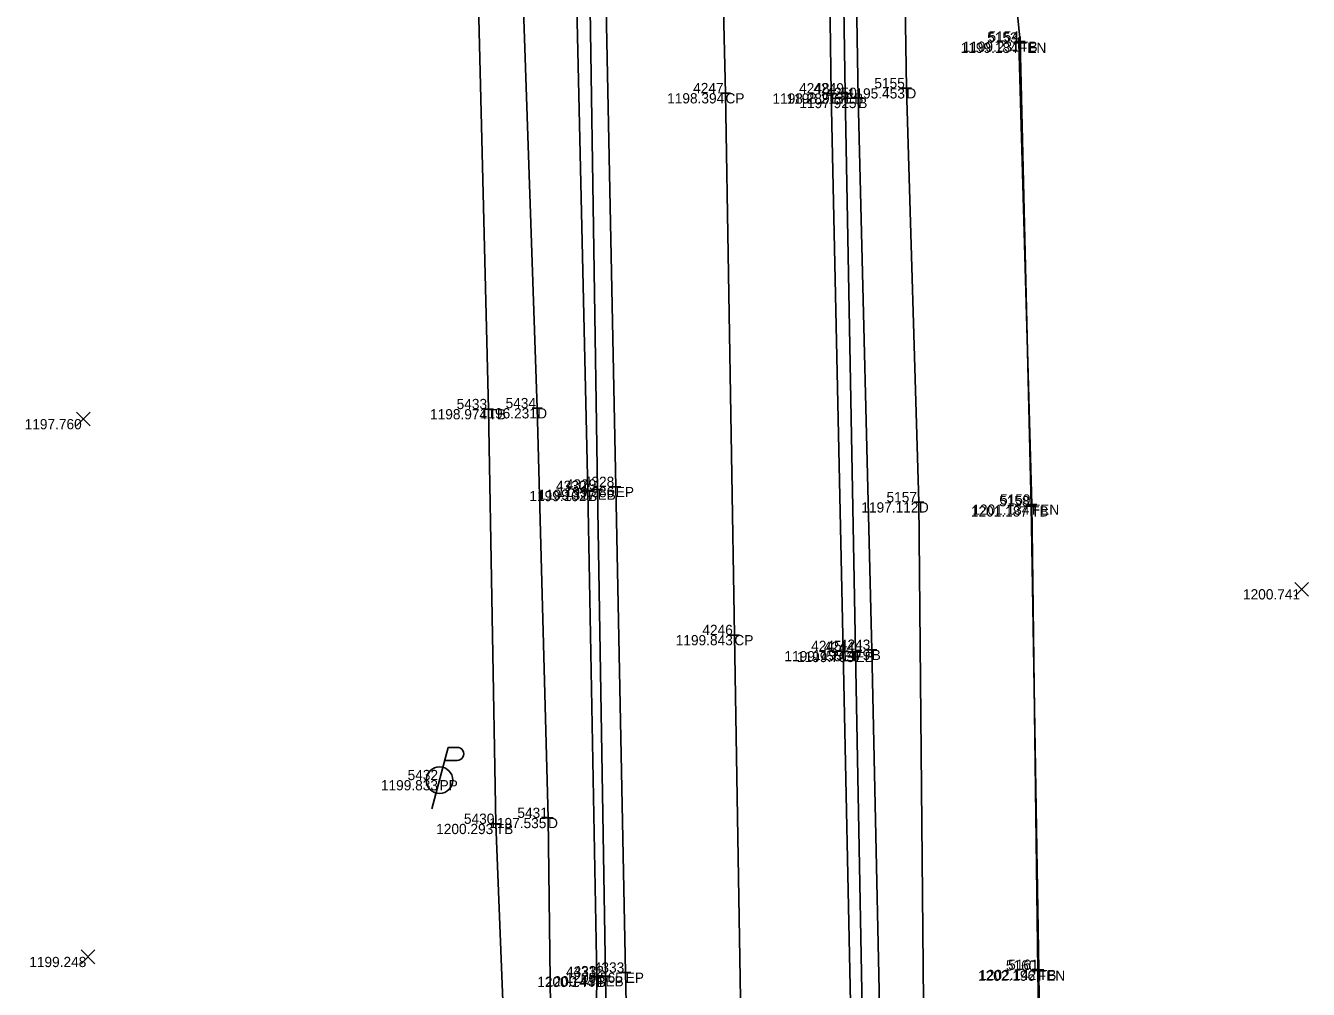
# Model space of a CAD drawing. Extents: x 2044996 to 2050343, y 455232 to 458054.
# Drawn here: x 2047551.1 to 2047676.4, y 457527.3 to 457621.4 of the extents above; entities that cross this region are included whole.
import ezdxf

# ---------------------------------------------------------------- set-up
doc = ezdxf.new("R2010")
doc.units = 0
for name, color, linetype in [('DR_X_Ditch', 7, 'Continuous'), ('DT_X_Contour_Minor', 7, 'Continuous'), ('DT_X_Contour_Text', 7, 'Continuous'), ('DT_X_Spot_Elev', 7, 'Continuous'), ('DT_X_Triangles', 7, 'Continuous'), ('DT_X_Void', 7, 'Continuous'), ('PV_X_COP', 7, 'Continuous'), ('PV_X_EOP', 7, 'Continuous'), ('PV_X_Shoulder_Aggregate', 7, 'Continuous'), ('RD_X_Fence', 7, 'Continuous'), ('SV_X_Break_Lines', 7, 'Continuous'), ('SV_X_Top_of_Bank', 7, 'Continuous'), ('UT_X_Electric_Cells', 7, 'Continuous')]:
    doc.layers.add(name, color=color, linetype=linetype)

msp = doc.modelspace()

# ---------------------------------------------------------------- linework, layer by layer
at = {"layer": 'DR_X_Ditch'}
for points in [[(2047603.88, 457240.71), (2047604.35, 457290.98), (2047605.27, 457322.96), (2047604.86, 457368.19), (2047603.19, 457417.51), (2047602.95, 457459.42), (2047602.66, 457501.84), (2047602.14, 457544.04), (2047601.08, 457584.06), (2047599.69, 457624.96), (2047599.4, 457669.27), (2047598.07, 457715.09), (2047597.97, 457762.92), (2047597.74, 457792.66), (2047596.26, 457838.2), (2047595.41, 457854.46)], [(2047635.93, 457828.45), (2047636.46, 457778.33), (2047635.67, 457731.58), (2047635.87, 457688.92), (2047636.59, 457650.58), (2047637.14, 457615.31), (2047638.36, 457574.87), (2047638.82, 457526.07), (2047639.21, 457482.92), (2047639.9, 457443.66), (2047641.24, 457398.66), (2047642.28, 457344.51), (2047644.03, 457300.89), (2047646.18, 457262.24), (2047646.96, 457237.04), (2047650.76, 457191.22), (2047650.42, 457143.89), (2047649.26, 457104.81), (2047651.9, 457052.9), (2047656.34, 457022.85)]]:
    msp.add_lwpolyline(points, dxfattribs=at)
at = {"layer": 'DT_X_Spot_Elev'}
for p, q in [((2047556.08, 457582.33), (2047557.41, 457583.67)), ((2047556.08, 457583.67), (2047557.41, 457582.33)), ((2047675.07, 457565.71), (2047676.41, 457567.05)), ((2047675.07, 457567.05), (2047676.41, 457565.71)), ((2047556.52, 457529.8), (2047557.86, 457531.14)), ((2047556.52, 457531.14), (2047557.86, 457529.8))]:
    msp.add_line(p, q, dxfattribs=at)
at = {"layer": 'DT_X_Void'}
for p, q in [((2047647.64, 457619.76), (2047648.64, 457619.76)), ((2047647.75, 457619.87), (2047648.75, 457619.87)), ((2047648.14, 457620.26), (2047648.14, 457619.26)), ((2047648.14, 457619.76), (2047648.14, 457619.76)), ((2047648.25, 457620.37), (2047648.25, 457619.37)), ((2047648.25, 457619.87), (2047648.25, 457619.87)), ((2047637.14, 457615.81), (2047637.14, 457614.81)), ((2047618.97, 457614.83), (2047619.97, 457614.83)), ((2047619.47, 457615.33), (2047619.47, 457614.33)), ((2047619.47, 457614.83), (2047619.47, 457614.83)), ((2047629.28, 457614.81), (2047630.28, 457614.81)), ((2047629.78, 457615.31), (2047629.78, 457614.31)), ((2047629.78, 457614.81), (2047629.78, 457614.81)), ((2047630.66, 457614.81), (2047631.66, 457614.81)), ((2047631.16, 457615.31), (2047631.16, 457614.31)), ((2047631.16, 457614.81), (2047631.16, 457614.81)), ((2047631.94, 457614.37), (2047632.94, 457614.37)), ((2047632.44, 457614.87), (2047632.44, 457613.87)), ((2047632.44, 457614.37), (2047632.44, 457614.37)), ((2047636.64, 457615.31), (2047637.64, 457615.31)), ((2047637.14, 457615.31), (2047637.14, 457615.31)), ((2047596.32, 457584.47), (2047596.32, 457583.47)), ((2047601.08, 457584.56), (2047601.08, 457583.56)), ((2047595.82, 457583.97), (2047596.82, 457583.97)), ((2047596.32, 457583.97), (2047596.32, 457583.97)), ((2047600.58, 457584.06), (2047601.58, 457584.06)), ((2047601.08, 457584.06), (2047601.08, 457584.06)), ((2047608.75, 457576.87), (2047608.75, 457575.87)), ((2047605.54, 457575.98), (2047606.54, 457575.98)), ((2047606.04, 457576.48), (2047606.04, 457575.48)), ((2047606.04, 457575.98), (2047606.04, 457575.98)), ((2047606.47, 457576.11), (2047607.47, 457576.11)), ((2047606.97, 457576.61), (2047606.97, 457575.61)), ((2047606.97, 457576.11), (2047606.97, 457576.11)), ((2047608.25, 457576.37), (2047609.25, 457576.37)), ((2047608.75, 457576.37), (2047608.75, 457576.37)), ((2047637.86, 457574.87), (2047638.86, 457574.87)), ((2047638.36, 457575.37), (2047638.36, 457574.37)), ((2047638.36, 457574.87), (2047638.36, 457574.87)), ((2047648.82, 457574.48), (2047649.82, 457574.48)), ((2047648.89, 457574.65), (2047649.89, 457574.65)), ((2047649.32, 457574.98), (2047649.32, 457573.98)), ((2047649.32, 457574.48), (2047649.32, 457574.48)), ((2047649.39, 457575.15), (2047649.39, 457574.15)), ((2047649.39, 457574.65), (2047649.39, 457574.65)), ((2047619.84, 457561.9), (2047620.84, 457561.9)), ((2047620.34, 457562.4), (2047620.34, 457561.4)), ((2047620.34, 457561.9), (2047620.34, 457561.9)), ((2047630.97, 457560.84), (2047630.97, 457559.84)), ((2047632.17, 457560.76), (2047632.17, 457559.76)), ((2047633.25, 457560.46), (2047634.25, 457560.46)), ((2047633.75, 457560.96), (2047633.75, 457559.96)), ((2047633.75, 457560.46), (2047633.75, 457560.46)), ((2047630.47, 457560.34), (2047631.47, 457560.34)), ((2047630.97, 457560.34), (2047630.97, 457560.34)), ((2047631.67, 457560.26), (2047632.67, 457560.26)), ((2047632.17, 457560.26), (2047632.17, 457560.26)), ((2047602.14, 457544.54), (2047602.14, 457543.54)), ((2047596.53, 457543.46), (2047597.53, 457543.46)), ((2047597.03, 457543.96), (2047597.03, 457542.96)), ((2047597.03, 457543.46), (2047597.03, 457543.46)), ((2047601.64, 457544.04), (2047602.64, 457544.04)), ((2047602.14, 457544.04), (2047602.14, 457544.04)), ((2047607.74, 457529.08), (2047607.74, 457528.08)), ((2047609.72, 457529.43), (2047609.72, 457528.43)), ((2047649.48, 457529.13), (2047650.48, 457529.13)), ((2047649.58, 457529.2), (2047650.58, 457529.2)), ((2047649.98, 457529.63), (2047649.98, 457528.63)), ((2047649.98, 457529.13), (2047649.98, 457529.13)), ((2047650.08, 457529.7), (2047650.08, 457528.7)), ((2047650.08, 457529.2), (2047650.08, 457529.2)), ((2047606.39, 457528.52), (2047607.39, 457528.52)), ((2047606.89, 457529.02), (2047606.89, 457528.02)), ((2047606.89, 457528.52), (2047606.89, 457528.52)), ((2047607.24, 457528.58), (2047608.24, 457528.58)), ((2047607.74, 457528.58), (2047607.74, 457528.58)), ((2047609.22, 457528.93), (2047610.22, 457528.93)), ((2047609.72, 457528.93), (2047609.72, 457528.93))]:
    msp.add_line(p, q, dxfattribs=at)
at = {"layer": 'PV_X_COP'}
msp.add_lwpolyline([(2047630.7, 457032.77), (2047629.57, 457079.46), (2047628.83, 457121.31), (2047627.83, 457168.37), (2047627.23, 457213.89), (2047626.35, 457261.41), (2047625.27, 457313.88), (2047624.14, 457367.69), (2047623.14, 457414.96), (2047622.16, 457463.48), (2047621.21, 457510.6), (2047620.34, 457561.9), (2047619.47, 457614.83), (2047618.33, 457662.23), (2047617.51, 457713.13), (2047616.39, 457759.38), (2047615.44, 457807.27), (2047614.41, 457854.52), (2047614.29, 457881.56), (2047613.16, 457931.14), (2047612.06, 457984.05), (2047611.48, 458032.26), (2047610.91, 458052.26)], dxfattribs=at)
at = {"layer": 'PV_X_EOP'}
for p, q in [((2047629.78, 457614.81), (2047629.22, 457661.11)), ((2047607.83, 457623.11), (2047608.75, 457576.37)), ((2047630.97, 457560.34), (2047629.78, 457614.81)), ((2047608.75, 457576.37), (2047609.72, 457528.93)), ((2047632.02, 457509.8), (2047630.97, 457560.34)), ((2047609.72, 457528.93), (2047610.65, 457484.6))]:
    msp.add_line(p, q, dxfattribs=at)
at = {"layer": 'PV_X_Shoulder_Aggregate'}
for p, q in [((2047606.24, 457622.99), (2047606.97, 457576.11)), ((2047606.97, 457576.11), (2047607.74, 457528.58)), ((2047607.74, 457528.58), (2047608.44, 457484.98))]:
    msp.add_line(p, q, dxfattribs=at)
msp.add_lwpolyline([(2047636.93, 457312.89), (2047635.93, 457367.47), (2047634.97, 457414.6), (2047633.92, 457462.12), (2047633.13, 457509.72), (2047632.17, 457560.26), (2047631.16, 457614.81), (2047630.46, 457661.29), (2047629.4, 457713.73), (2047628.5, 457758.09), (2047627.36, 457807.43), (2047627.48, 457822.09), (2047628.61, 457825.87), (2047628.68, 457844.07), (2047627.2, 457879.15), (2047626.26, 457880.5), (2047625.13, 457929.52), (2047623.96, 457984.29), (2047622.9, 458032.45), (2047622.9, 458052.72)], dxfattribs=at)
at = {"layer": 'RD_X_Fence'}
msp.add_lwpolyline([(2047648.14, 457619.76), (2047649.39, 457574.65), (2047649.98, 457529.13), (2047650.66, 457480.39), (2047651.7, 457447.16), (2047652.23, 457398.03), (2047653.85, 457346.51), (2047654.21, 457298.97), (2047654.82, 457261.49), (2047656.66, 457189.93), (2047656.98, 457146.63), (2047657.53, 457104.26), (2047658.63, 457057.97)], dxfattribs=at)
at = {"layer": 'SV_X_Break_Lines'}
for points in [[(2047600.59, 457854.75), (2047601.57, 457806.15), (2047602.51, 457762.55), (2047603.42, 457715.8), (2047604.03, 457669.25), (2047604.95, 457623.23), (2047606.04, 457575.98), (2047606.89, 457528.52), (2047606.36, 457485.08), (2047608.62, 457438.46), (2047609.61, 457393.11), (2047610.32, 457343.26)], [(2047638.13, 457312.9), (2047637.8, 457367.1), (2047636.31, 457414.94), (2047635.39, 457462.19), (2047634.84, 457510.57), (2047633.75, 457560.46), (2047632.44, 457614.37), (2047631.64, 457661.27), (2047630.56, 457713.53), (2047629.28, 457758.04), (2047628.78, 457808.04), (2047629.36, 457824.93)]]:
    msp.add_lwpolyline(points, dxfattribs=at)
at = {"layer": 'SV_X_Top_of_Bank'}
for points in [[(2047602.07, 457232.89), (2047595.37, 457236.81), (2047596.56, 457240.43), (2047601.59, 457243.99), (2047601.86, 457291.34), (2047601.11, 457323.06), (2047599.87, 457367.88), (2047599.04, 457416.36), (2047598.26, 457460), (2047598.65, 457502.28), (2047597.03, 457543.46), (2047596.32, 457583.97), (2047595.27, 457626.15), (2047595.52, 457669.28), (2047593.7, 457715), (2047590.76, 457760.29), (2047587.57, 457790.55), (2047585.9, 457853.96)], [(2047640.57, 457829.63), (2047642.73, 457776.65), (2047644.22, 457735.31), (2047644.62, 457692.67), (2047644.93, 457653.27), (2047648.25, 457619.87), (2047649.32, 457574.48), (2047650.08, 457529.2), (2047650.6, 457480.31), (2047651.65, 457447.12), (2047652.29, 457398.02), (2047653.83, 457346.33), (2047654.34, 457298.99), (2047654.68, 457261.41), (2047656.79, 457189.89), (2047656.98, 457146.62), (2047657.59, 457104.22), (2047658.54, 457057.89), (2047659.73, 457026.44)]]:
    msp.add_lwpolyline(points, dxfattribs=at)
at = {"layer": 'UT_X_Electric_Cells'}
for p, q in [((2047592.39, 457550.93), (2047590.79, 457544.93)), ((2047592.39, 457550.93), (2047593.24, 457550.93)), ((2047592.05, 457549.65), (2047593.24, 457549.65))]:
    msp.add_line(p, q, dxfattribs=at)
msp.add_circle((2047591.54, 457547.73), 1.3, dxfattribs=at)
msp.add_arc((2047593.26, 457550.29), 0.638, 268.8767, 91.1233, dxfattribs=at)

# ---------------------------------------------------------------- texts
at = {"layer": 'DT_X_Contour_Minor'}
for s, p in [('1199.184', (2047642.44, 457618.76)), ('1199.231', (2047642.63, 457618.87)), ('1198.394', (2047613.77, 457613.83)), ('1198.289', (2047624.06, 457613.81)), ('1198.213', (2047625.43, 457613.81)), ('1197.925', (2047626.69, 457613.37)), ('1195.453', (2047631.42, 457614.31)), ('1197.760', (2047551.01, 457582)), ('1198.974', (2047590.61, 457582.97)), ('1196.231', (2047595.47, 457583.06)), ('1199.102', (2047600.31, 457574.98)), ('1199.317', (2047601.19, 457575.11)), ('1199.386', (2047603.02, 457575.37)), ('1197.112', (2047632.74, 457573.87)), ('1201.187', (2047643.44, 457573.48)), ('1201.134', (2047643.58, 457573.65)), ('1200.741', (2047670.02, 457565.38)), ('1199.843', (2047614.61, 457560.9)), ('1199.479', (2047628.03, 457559.46)), ('1199.755', (2047625.23, 457559.34)), ('1199.703', (2047626.45, 457559.26)), ('1199.833', (2047585.81, 457546.73)), ('1200.293', (2047591.21, 457542.46)), ('1197.535', (2047596.4, 457543.04)), ('1199.248', (2047551.46, 457529.47)), ('1202.196', (2047644.14, 457528.13)), ('1202.142', (2047644.25, 457528.2)), ('1200.144', (2047601.08, 457527.52)), ('1200.434', (2047601.93, 457527.58)), ('1200.565', (2047603.87, 457527.93))]:
    msp.add_text(s, height=1, dxfattribs=at).set_placement(p)
at = {"layer": 'DT_X_Contour_Text'}
for s, p in [('FEN', (2047648.14, 457618.76)), ('TB', (2047648.25, 457618.87)), ('CP', (2047619.47, 457613.83)), ('EP', (2047629.78, 457613.81)), ('EB', (2047631.16, 457613.81)), ('B', (2047632.44, 457613.37)), ('D', (2047637.14, 457614.31)), ('TB', (2047596.32, 457582.97)), ('D', (2047601.08, 457583.06)), ('B', (2047606.04, 457574.98)), ('EB', (2047606.97, 457575.11)), ('EP', (2047608.75, 457575.37)), ('D', (2047638.36, 457573.87)), ('TB', (2047649.32, 457573.48)), ('FEN', (2047649.39, 457573.65)), ('CP', (2047620.34, 457560.9)), ('B', (2047633.75, 457559.46)), ('EP', (2047630.97, 457559.34)), ('EB', (2047632.17, 457559.26)), ('PP', (2047591.54, 457546.73)), ('TB', (2047597.03, 457542.46)), ('D', (2047602.14, 457543.04)), ('FEN', (2047649.98, 457528.13)), ('TB', (2047650.08, 457528.2)), ('B', (2047606.89, 457527.52)), ('EB', (2047607.74, 457527.58)), ('EP', (2047609.72, 457527.93))]:
    msp.add_text(s, height=1, dxfattribs=at).set_placement(p)
at = {"layer": 'DT_X_Triangles'}
for s, p in [('5153', (2047645.03, 457619.76)), ('5154', (2047645.16, 457619.87)), ('4247', (2047616.31, 457614.83)), ('4248', (2047626.66, 457614.81)), ('4249', (2047628.06, 457614.81)), ('5155', (2047634.01, 457615.31)), ('4250', (2047629.32, 457614.37)), ('5433', (2047593.21, 457583.97)), ('5434', (2047597.99, 457584.06)), ('4330', (2047602.92, 457575.98)), ('4329', (2047603.87, 457576.11)), ('4328', (2047605.63, 457576.37)), ('5157', (2047635.2, 457574.87)), ('5158', (2047646.2, 457574.48)), ('5159', (2047646.29, 457574.65)), ('4246', (2047617.21, 457561.9)), ('4245', (2047627.84, 457560.34)), ('4244', (2047629.08, 457560.26)), ('4243', (2047630.64, 457560.46)), ('5432', (2047588.42, 457547.73)), ('5430', (2047593.92, 457543.46)), ('5431', (2047599.14, 457544.04)), ('4331', (2047603.89, 457528.52)), ('4332', (2047604.62, 457528.58)), ('4333', (2047606.61, 457528.93)), ('5160', (2047646.86, 457529.13)), ('5161', (2047647.08, 457529.2))]:
    msp.add_text(s, height=1, dxfattribs=at).set_placement(p)

doc.saveas('drawing.dxf')
